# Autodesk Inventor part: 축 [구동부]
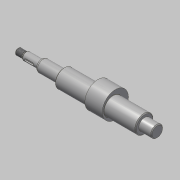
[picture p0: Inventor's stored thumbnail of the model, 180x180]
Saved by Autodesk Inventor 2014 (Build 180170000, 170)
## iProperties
Created: 2015-12
Part Number: 축 [구동부]
Document SubType Name: Modeling
Designer: mdu
Density: 7.86 g/cm^3
Material: 강철, 연강
Appearance: 강철
Mass: 484.678 g
Surface Area: 125.968 cm^2
Volume: 61.6639 cm^3
Author: mdu
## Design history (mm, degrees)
sketch "스케치1"
  geometry: L1 (62, 100.9)-(62, 67.1) reference; L2 (51, 101.2)-(51, 84) reference; L3 (-51, 84)-(-51, 101.2) reference; L4 (-62, 67.1)-(-62, 100.9) reference; L5 (-51.6, 91.5)-(-61.4, 91.5) reference; L6 (51.6, 91.5)-(61.4, 91.5) reference; L7 (67, 84)-(-109, 84); L8 (-77, 64.201)-(-77, 103.799) reference; L9 (67, 84)-(67, 91.5); L10 (67, 91.5)-(51, 91.5); L11 (51, 91.5)-(51, 95.5); L12 (51, 95.5)-(-51, 95.5); L13 (-51, 95.5)-(-51, 91.5); L14 (-51, 91.5)-(-79, 91.5); L15 (-79, 91.5)-(-79, 89); L16 (-79, 89)-(-99, 89); L17 (-99, 89)-(-99, 87); L18 (-100.5, 88)-(-109, 88); L19 (-109, 88)-(-109, 84); L20 (-99, 87)-(-100.5, 87); L21 (-100.5, 87)-(-100.5, 88); 2 further points
  constraints: 32 end point, 7 parallel, 6 point on line, 5 perpendicular, 2 collinear, 2 horizontal, 1 midpoint, 4 other
  dimensions: "d0" = 5 distance from line of L7.start L1; "d2" = 2 distance between parallel lines of L15 L8; "d3" = 23 diameter of L12 L7; "d4" = 10 diameter of L16 L7; "d5" = 1.5 distance of L17.end L20.end; "d6" = 6 diameter of L20 L7; "d7" = 20 distance of L15.end L16.end; "d8" = 10 distance between parallel lines of L17 L19; "d9" = 8 diameter of L18 L7
revolve "회전1" sketch "스케치1" stored, may be unused: angle "d10" = 90 deg
sketch "스케치2"
  geometry: C1 r 11.5 at (84, 0) reference; C2 r 11.5 at (84, 0) reference; C3 r 16.5 at (87, 0); 1 further point
  constraints: 1 centre point, 1 horizontal alignment
  dimensions: "d11" = 33 diameter of C3; "d12" = 3 distance of C3.centre C1.centre
extrude "돌출1" join sketch "스케치2" stored distance "d13" = 22; taper "d14" = 0 deg
chamfer "모따기1" distance "d15" = 1; stored, may be unused: second distance "d16" = 2, angle "d17" = 45 deg
feature "스레드1" dims "d18" = 10, "d19" = 0
node "작업 평면1"
sketch "스케치3"
  geometry: L1 (-5.5, -1.5)-(3.5, -1.5); L2 (3.5, 1.5)-(-5.5, 1.5); L3 (-10, -4)-(-10, 4) reference; A1 r 1.5 centre (3.5, 0) between (3.5, -1.5) and (3.5, 1.5); A2 r 1.5 centre (-5.5, 0) between (-5.5, 1.5) and (-5.5, -1.5); 2 further points
  constraints: 4 end point, 4 point on circle, 4 tangent, 2 centre point, 1 horizontal, 1 horizontal alignment, 1 midpoint, 1 parallel
  dimensions: "d20" = 3 distance between parallel lines of L1 L2; "d21" = 12 dimension on A1 A2; "d22" = 3 distance edge to line of A2 L3
extrude "돌출2" cut sketch "스케치3" distance "d23" = 1.8; taper "d24" = 0 deg
fillet "모깎기1" dims "d25" = 0.3
fillet "모깎기2" dims "d26" = 3
node "솔리드1"
node "참조1"
node "참조2"
node "참조3"
node "참조4"
node "참조5"
node "투영된 루프1"
